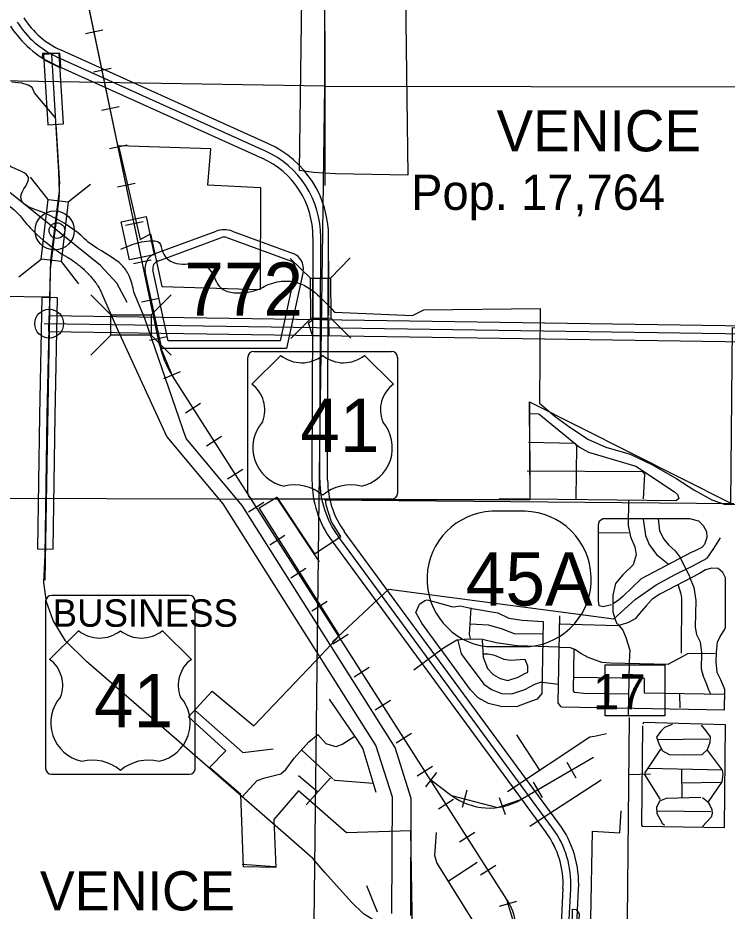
# Model space of a CAD drawing. Extents: x 408847 to 817539, y 923858 to 1151780.
# Drawn here: x 511231 to 520291, y 998249 to 1009652 of the extents above; entities that cross this region are included whole.
import ezdxf

# ---------------------------------------------------------------- set-up
doc = ezdxf.new("R2010")
doc.units = 0
for name, color, linetype in [('Airport Names', 7, 'Continuous'), ('Bridges', 7, 'Continuous'), ('Cities Incorporated Area', 7, 'Continuous'), ('Cities Incorporated Linear Boundaries', 7, 'Continuous'), ('County Route Divided Highway Outline and Fill', 7, 'Continuous'), ('Lakes and Ponds', 7, 'Continuous'), ('Level 12', 7, 'Continuous'), ('Level 23', 7, 'Continuous'), ('Level 3', 7, 'Continuous'), ('Level 39', 7, 'Continuous'), ('Level 43', 7, 'Continuous'), ('Level 6', 7, 'Continuous'), ('Local Roads Paved', 7, 'Continuous'), ('Masks for Road Features', 7, 'Continuous'), ('Narrow River Creek and Branch and Slough', 7, 'Continuous'), ('Planning Number US Highways', 7, 'Continuous'), ('Railroads', 7, 'Continuous'), ('Roadshields County Roads', 7, 'Continuous'), ('Roadshields US Highways', 7, 'Continuous'), ('Roadshields US Highways Business', 7, 'Continuous'), ('Section Lines', 7, 'Continuous'), ('Town Centers', 7, 'Continuous'), ('US Route Divided Highway Outline and Fill', 7, 'Continuous'), ('US Routes Highway Center Lines', 7, 'Continuous')]:
    doc.layers.add(name, color=color, linetype=linetype)

msp = doc.modelspace()

# ---------------------------------------------------------------- linework, layer by layer
at = {"layer": 'Bridges'}
for p, q in [((511618, 1007334), (511394, 1007618)), ((511873, 1007304), (512157, 1007528)), ((511529, 1006571), (511618, 1007334)), ((511618, 1007334), (511873, 1007304)), ((511873, 1007304), (511783, 1006541)), ((511245, 1006347), (511529, 1006571)), ((511783, 1006541), (511529, 1006571)), ((514968, 1006328), (514709, 1006582)), ((515224, 1006330), (515477, 1006588)), ((511783, 1006541), (512007, 1006257)), ((512420, 1005859), (512164, 1006115)), ((512932, 1005859), (513188, 1006115)), ((514972, 1005816), (514718, 1005558)), ((515228, 1005818), (515486, 1005564)), ((512420, 1005603), (512164, 1005347)), ((512932, 1005603), (513188, 1005347)), ((515683, 998576), (515820, 998240))]:
    msp.add_line(p, q, dxfattribs=at)
for points in [[(515224, 1006330), (515228, 1005818), (514972, 1005816), (514968, 1006328)], [(512420, 1005859), (512932, 1005859), (512932, 1005603), (512420, 1005603)]]:
    msp.add_lwpolyline(points, close=True, dxfattribs=at)
msp.add_circle((511701, 1006938), 250, dxfattribs=at)
at = {"layer": 'Cities Incorporated Area'}
for p, q in [((512516, 1008020), (512793, 1006823)), ((513696, 1007981), (512516, 1008020)), ((513659, 1007516), (513696, 1007981)), ((514336, 1007484), (513659, 1007516)), ((514332, 1006184), (514336, 1007484)), ((512793, 1006823), (512925, 1006893)), ((512925, 1006893), (513070, 1006223)), ((513070, 1006223), (514332, 1006184)), ((517768, 1004746), (517770, 1003510)), ((515085, 1002706), (514535, 1003532)), ((517770, 1003503), (515351, 1003501)), ((514096, 998850), (514513, 998820))]:
    msp.add_line(p, q, dxfattribs=at)
at = {"layer": 'Cities Incorporated Linear Boundaries'}
msp.add_line((514078, 999738), (513680, 1000083), dxfattribs=at)
for points in [[(515288, 1007663), (515007, 1007676), (514828, 1007705), (514888, 1012104), (514056, 1012044), (513225, 1011836), (513154, 1011755), (513147, 1011502), (512894, 1011153), (512686, 1010848), (512315, 1010521), (512100, 1010499), (512048, 1010573), (512078, 1010707), (512144, 1010870), (512167, 1010945), (512115, 1011041), (512048, 1011116), (511951, 1011123), (511647, 1010960), (511201, 1010811)], [(515147, 1012047), (515730, 1012047), (515730, 1010579), (516172, 1010579), (516212, 1007643), (515288, 1007663)], [(517768, 1004750), (520337, 1003455), (520360, 1005699), (523174, 1005695)], [(515344, 1003504), (517774, 1003504), (517768, 1004750)], [(514314, 1003398), (514539, 1003532), (515019, 1002811)], [(515019, 1002811), (515355, 1003031), (515237, 1003217), (515170, 1003433), (515162, 1003507), (515344, 1003504)], [(515104, 1001517), (515341, 1001768), (514314, 1003398)], [(513680, 1000083), (513886, 1000296), (513412, 1000730), (513713, 1001058), (514247, 1000615), (515104, 1001517)], [(511321, 990703), (516273, 990804), (516322, 994864), (516249, 999275), (515429, 999250), (514815, 999785), (514500, 999420), (514527, 998807), (514111, 998813), (514078, 999738)]]:
    msp.add_lwpolyline(points, dxfattribs=at)
at = {"layer": 'County Route Divided Highway Outline and Fill'}
for p, q in [((511625, 1005848), (511622, 1005648)), ((531173, 1005564), (511625, 1005848)), ((511565, 1005749), (531172, 1005464)), ((511622, 1005648), (531170, 1005364))]:
    msp.add_line(p, q, dxfattribs=at)
msp.add_lwpolyline([(518361, 998268), (518400, 998213), (518391, 998056), (518345, 998037), (518311, 998031), (518317, 998276)], close=True, dxfattribs=at)
at = {"layer": 'Lakes and Ponds'}
for points in [[(512307, 1006120), (512502, 1005674)], [(512852, 1005816), (512713, 1006150)], [(516249, 998194), (516256, 999688), (516049, 1000339), (514095, 1003427), (513379, 1004282), (512852, 1005816)], [(512502, 1005674), (513134, 1004303), (513851, 1003448), (515805, 1000360), (516012, 999709), (516005, 998219)]]:
    msp.add_lwpolyline(points, dxfattribs=at)
for points in [[(511580, 1007158), (511270, 1007376), (511365, 1007615), (511150, 1007748), (510986, 1007875), (510761, 1008043), (510597, 1008166), (510507, 1008232), (510351, 1008560), (510536, 1008801), (510589, 1008929), (510519, 1009171), (510466, 1009314), (510396, 1009548), (510478, 1009753), (510603, 1010176), (510610, 1010188)], [(510194, 1008136), (510178, 1008059), (510176, 1007945), (510170, 1007704), (510189, 1007514), (510339, 1007341), (510589, 1007316), (510837, 1007304), (511050, 1007289), (511254, 1007128), (511433, 1006925), (511793, 1006637)], [(512713, 1006150), (512657, 1006351), (512572, 1006481), (512129, 1006790), (512040, 1006872), (511580, 1007158)], [(511793, 1006637), (511834, 1006614), (511873, 1006592), (511942, 1006547), (511999, 1006504), (512047, 1006465), (512087, 1006428), (512121, 1006394), (512149, 1006364), (512196, 1006308), (512229, 1006264), (512252, 1006230), (512284, 1006177), (512307, 1006120)]]:
    msp.add_spline(points, degree=3, dxfattribs=at)
at = {"layer": 'Level 12'}
msp.add_lwpolyline([(514942, 1005759), (515006, 1005804), (515186, 1005805), (515201, 1005791), (515204, 1005606), (515185, 1005590), (515004, 1005591), (514989, 1005611)], close=True, dxfattribs=at)
msp.add_circle((511730, 1006937), 99.8, dxfattribs=at)
at = {"layer": 'Level 23'}
msp.add_lwpolyline([(512870, 1007117), (512974, 1006628), (512656, 1006561), (512552, 1007050)], close=True, dxfattribs=at)
at = {"layer": 'Level 3'}
for p, q in [((517657, 999673), (518584, 1000214)), ((516508, 999926), (516771, 999727))]:
    msp.add_line(p, q, dxfattribs=at)
msp.add_arc((517254, 1000365), 800, 232.8792, 300.2321, dxfattribs=at)
at = {"layer": 'Level 39'}
msp.add_lwpolyline([(518733, 1001394), (519496, 1001394), (519496, 1000742), (518733, 1000742)], close=True, dxfattribs=at)
at = {"layer": 'Level 6'}
for p, q in [((514434, 1008043), (511783, 1009238)), ((511701, 1009056), (514352, 1007860)), ((511714, 1008291), (511762, 1007535)), ((511758, 1007386), (511650, 1006511)), ((515000, 1006853), (514988, 1003751)), ((515188, 1003750), (515200, 1006853)), ((514997, 1006544), (514997, 1005794)), ((515197, 1006544), (515197, 1005854)), ((511644, 1006426), (511640, 1006154)), ((511640, 1006162), (511574, 1002475)), ((518143, 999367), (515401, 1003094)), ((515240, 1002975), (517981, 999248)), ((518194, 998539), (518078, 996325)), ((518278, 996315), (518394, 998529))]:
    msp.add_line(p, q, dxfattribs=at)
for centre, radius, start, end in [((512236, 1010241), 1100, 212.3802, 245.7197), ((512236, 1010241), 1300, 212.3802, 245.7197), ((513900, 1006858), 1300, 359.7797, 65.7197), ((513900, 1006858), 1100, 359.7797, 65.7197), ((510964, 1007484), 800, 352.9475, 3.6329), ((512444, 1006413), 800, 172.9475, 179.1018), ((516288, 1003746), 1300, 179.7796, 216.3338), ((516288, 1003746), 1100, 179.7796, 216.3338), ((517095, 998597), 1300, 357.0178, 36.3338), ((517095, 998597), 1100, 357.0178, 36.3338)]:
    msp.add_arc(centre, radius, start, end, dxfattribs=at)
at = {"layer": 'Local Roads Paved'}
for p, q in [((511638, 1006088), (509765, 1006105)), ((519029, 1003079), (518650, 1003072)), ((519684, 1001017), (519687, 1000844)), ((519040, 1000719), (519015, 998143)), ((517897, 1000047), (517603, 1000498)), ((519403, 1000439), (520055, 1000449)), ((514853, 1000306), (515255, 999937)), ((519241, 1000012), (519442, 1000317)), ((519275, 1000076), (520231, 1000052)), ((519707, 1000056), (519712, 999693)), ((515057, 999771), (514817, 999978)), ((514913, 999606), (515226, 999952)), ((519040, 999993), (519314, 1000003)), ((519236, 999993), (519437, 999674)), ((517770, 999335), (518682, 999924)), ((519707, 999885), (520207, 999895)), ((520084, 999517), (519403, 999527)), ((516726, 998631), (517098, 998874))]:
    msp.add_line(p, q, dxfattribs=at)
for points in [[(515139, 1019358), (515153, 1007511)], [(511712, 1008375), (511445, 1008694), (511414, 1008762), (511362, 1008792), (511282, 1008820), (511153, 1008832)], [(517764, 1004602), (517885, 1004599), (518407, 1004172), (518521, 1004109), (519125, 1003929), (519617, 1003601), (519658, 1003568), (519676, 1003517), (519639, 1003487), (517377, 1003513)], [(517753, 1004234), (518345, 1004223), (518367, 1004190), (518359, 1003506)], [(517738, 1003870), (519205, 1003863), (519224, 1003844), (519235, 1003826), (519220, 1003513)], [(519033, 1003487), (519025, 1003171), (519055, 1003027), (519110, 1002899), (519128, 1002799), (519091, 1002670), (518959, 1002542), (518867, 1002432), (518830, 1002281), (518830, 1002071), (518856, 1001983), (518882, 1001917)], [(518812, 1002159), (518760, 1002145), (518709, 1002134), (518657, 1002148), (518646, 1002211), (518646, 1003186), (518661, 1003230), (518702, 1003260), (518731, 1003260), (519812, 1003263), (519926, 1003230), (519985, 1003171), (520029, 1003094), (520033, 1003017), (520000, 1002928), (519967, 1002892), (519952, 1002881), (519882, 1002848), (519831, 1002825), (519194, 1002491), (518963, 1002270), (518900, 1002215), (518841, 1002178)], [(519220, 1003252), (519246, 1003046), (519294, 1002928), (519389, 1002800), (519536, 1002682)], [(519408, 1003256), (519426, 1003105), (519481, 1002998), (519544, 1002925), (519625, 1002848), (519691, 1002763), (519698, 1002748), (519812, 1002520)], [(518150, 1002017), (518128, 1000910), (518161, 1000862), (518179, 1000858), (520257, 1000818), (520261, 1001079), (520210, 1001201), (520165, 1001296), (520151, 1001433), (520154, 1001554), (520169, 1001683), (520202, 1001753), (520257, 1001841), (520268, 1001870), (520272, 1002503), (520235, 1002573), (520176, 1002621), (520096, 1002629), (520015, 1002606), (519937, 1002559), (519430, 1002297), (519334, 1002231), (519257, 1002146), (519172, 1002047), (519117, 1001981), (519029, 1001933), (518926, 1001900), (518889, 1001893), (518139, 1001911)], [(519812, 1002518), (519867, 1002382), (519890, 1002216), (519882, 1001874), (519901, 1001782), (519948, 1001686), (519963, 1001547), (519959, 1001341), (519985, 1001249), (520026, 1001146), (520051, 1001076), (520077, 1001024)], [(519665, 1002412), (519698, 1002298), (519709, 1002250), (519702, 1001540)], [(516643, 1001580), (516393, 1001923), (516316, 1002059), (516360, 1002166), (516430, 1002213), (516459, 1002221), (516559, 1002199), (516772, 1002136), (516801, 1002132), (516879, 1002147), (517033, 1002114), (517364, 1002055), (517504, 1001989), (517673, 1001963), (517942, 1001948), (517923, 1001025), (517864, 1000955), (517743, 1000914), (517600, 1000855), (517401, 1000863), (517243, 1000900), (517110, 1000973), (517011, 1001076), (516636, 1001588)], [(517018, 1002121), (516996, 1001779), (517007, 1001731)], [(517011, 1001915), (517239, 1001904), (517405, 1001856), (517570, 1001794), (517931, 1001787)], [(518889, 1001915), (518959, 1001834), (518999, 1001742), (519047, 1001580), (519040, 1001425), (519025, 1000755)], [(518144, 1001617), (517603, 1001636), (517342, 1001676), (517166, 1001717), (516978, 1001720), (516838, 1001706), (516669, 1001606), (516290, 1001327)], [(516849, 1001702), (516893, 1001533), (517184, 1001146), (517280, 1001080), (517408, 1001025), (517541, 1001021), (517706, 1001080), (517835, 1001146), (517905, 1001172), (517931, 1001172), (518137, 1001146)], [(517162, 1001706), (517173, 1001492), (517232, 1001345), (517302, 1001271), (517390, 1001220), (517489, 1001194), (517622, 1001235), (517699, 1001279), (517743, 1001301), (517743, 1001378), (517710, 1001459), (517522, 1001448), (517441, 1001463), (517324, 1001511), (517239, 1001529), (517166, 1001529)], [(518150, 1001617), (518286, 1001613), (518352, 1001587), (518426, 1001539), (518510, 1001491), (518573, 1001469), (518687, 1001429), (518805, 1001418), (519536, 1001403), (519720, 1001499), (519790, 1001536), (519996, 1001543), (520140, 1001539)], [(518334, 1001591), (518326, 1001061), (518337, 1001046), (518382, 1001039), (518455, 1001031), (519029, 1001024)], [(520254, 1001013), (519235, 1001031), (519235, 1001219), (518341, 1001230)], [(515207, 1000956), (515568, 1000426), (515638, 1000320), (515803, 999768)], [(513493, 1000813), (514104, 1000272), (514494, 1000320)], [(519211, 1000616), (519197, 999345), (519207, 999335), (520256, 999316), (520271, 1000626), (519221, 1000655), (519216, 1000635)], [(519589, 1000631), (519491, 1000591), (519442, 1000547), (519388, 1000469), (519422, 1000375), (519466, 1000297), (519550, 1000248), (519741, 1000243), (519972, 1000248), (520040, 1000312), (520075, 1000405), (520079, 1000474), (520021, 1000552), (519962, 1000621)], [(517485, 999777), (518535, 1000474), (518598, 1000483), (518750, 1000518)], [(514098, 999706), (514288, 999915), (514387, 999952), (514589, 1000003), (514652, 1000055), (514759, 1000202), (514946, 1000408), (515061, 1000505)], [(515534, 1000477), (515384, 1000382), (515292, 1000346), (515171, 1000386), (515061, 1000505)], [(520035, 1000302), (520227, 1000047), (520236, 999998), (520222, 999899), (520050, 999644)], [(515262, 999930), (515281, 999919), (515768, 999884)], [(519957, 999698), (519511, 999688), (519427, 999654), (519388, 999571), (519393, 999497), (519437, 999419), (519462, 999370), (519491, 999345)], [(519976, 999698), (520040, 999649), (520070, 999600), (520094, 999546), (520099, 999492), (520089, 999448), (520026, 999384), (519976, 999330)], [(518549, 998146), (518569, 999271), (518922, 999247), (518937, 999531)], [(516573, 999252), (516553, 998958), (516583, 998860), (517068, 998084), (517103, 998030)]]:
    msp.add_lwpolyline(points, dxfattribs=at)
at = {"layer": 'Masks for Road Features'}
msp.add_lwpolyline([(511542, 1009150), (511582, 1009108), (511758, 1009024), (511780, 1009030), (511766, 1009202), (511546, 1009196)], close=True, dxfattribs=at)
at = {"layer": 'Narrow River Creek and Branch and Slough'}
for p, q in [((515275, 1005895), (516270, 1005852)), ((516270, 1005852), (516417, 1005926)), ((516417, 1005926), (517902, 1005940)), ((517902, 1005940), (517895, 1004734)), ((517895, 1004734), (518094, 1004565)), ((518094, 1004565), (518282, 1004426)), ((518282, 1004426), (518522, 1004269)), ((518522, 1004269), (518742, 1004172)), ((518742, 1004172), (519053, 1004082)), ((519053, 1004082), (519331, 1003952)), ((519331, 1003952), (519650, 1003768)), ((519650, 1003768), (519867, 1003629)), ((519867, 1003629), (520097, 1003500)), ((520097, 1003500), (520266, 1003441)), ((520266, 1003441), (520433, 1003445)), ((520119, 1002877), (520207, 1003016)), ((520035, 1002753), (520119, 1002877)), ((519853, 1002657), (520035, 1002753)), ((519626, 1002548), (519853, 1002657)), ((519383, 1002416), (519626, 1002548)), ((515251, 1001688), (515970, 1002360)), ((515970, 1002360), (518844, 1001981)), ((519116, 1002225), (519383, 1002416)), ((518844, 1001981), (519116, 1002225))]:
    msp.add_line(p, q, dxfattribs=at)
msp.add_lwpolyline([(512628, 1006019), (512494, 1006267), (512288, 1006490), (510641, 1007809)], dxfattribs=at)
msp.add_spline([(512547, 1006701), (512660, 1006746), (512913, 1006806), (513037, 1006784), (513081, 1006660), (513335, 1006507), (513577, 1006511), (513720, 1006382), (513753, 1006311), (513819, 1006210), (513972, 1006146), (514149, 1006148), (514308, 1006188), (514402, 1006234), (514517, 1006275), (514739, 1006286), (515275, 1005895)], degree=3, dxfattribs=at)
at = {"layer": 'Planning Number US Highways'}
for p, q in [((517709, 1003354), (517285, 1003354)), ((517217, 1001626), (517770, 1001626))]:
    msp.add_line(p, q, dxfattribs=at)
for centre, radius, start, end in [((517324, 1002487), 867, 92.5588, 262.9755), ((517689, 1002488), 866, 275.316, 88.7032)]:
    msp.add_arc(centre, radius, start, end, dxfattribs=at)
at = {"layer": 'Railroads'}
for p, q in [((513042, 1005482), (511050, 1014994)), ((512093, 1009452), (512318, 1009499)), ((512196, 1008963), (512421, 1009010)), ((512298, 1008474), (512523, 1008521)), ((512401, 1007984), (512626, 1008031)), ((512503, 1007495), (512728, 1007542)), ((512606, 1007005), (512831, 1007053)), ((512708, 1006516), (512933, 1006563)), ((512811, 1006027), (513036, 1006074)), ((512913, 1005537), (513138, 1005584)), ((513094, 1005050), (513307, 1005137)), ((517478, 998398), (513206, 1005081)), ((513371, 1004609), (513565, 1004733)), ((513640, 1004188), (513834, 1004312)), ((513910, 1003767), (514103, 1003891)), ((514179, 1003346), (514373, 1003469)), ((514448, 1002924), (514642, 1003048)), ((514718, 1002503), (514911, 1002627)), ((514987, 1002082), (515181, 1002206)), ((515256, 1001660), (515450, 1001784)), ((515525, 1001239), (515719, 1001363)), ((515795, 1000818), (515989, 1000942)), ((516064, 1000397), (516258, 1000520)), ((516333, 999975), (516527, 1000099)), ((518244, 1000149), (518360, 999950)), ((516577, 1000018), (516438, 999834)), ((517812, 999897), (517928, 999698)), ((516965, 999795), (516906, 999572)), ((516603, 999554), (516796, 999678)), ((517380, 999700), (517455, 999483)), ((516872, 999133), (517066, 999257)), ((517141, 998711), (517335, 998835)), ((517383, 998313), (517604, 998378))]:
    msp.add_line(p, q, dxfattribs=at)
for points in [[(517607, 997362), (517604, 997971), (517604, 997971), (517478, 998398), (517478, 998398), (513206, 1005081), (513206, 1005081), (513042, 1005482), (513042, 1005482), (511050, 1014994), (510079, 1019797), (501500, 1060485)], [(516508, 999926), (516771, 999727), (516771, 999727), (517359, 999571), (517657, 999673), (517657, 999673), (518584, 1000214)]]:
    msp.add_lwpolyline(points, dxfattribs=at)
for centre, radius, start, end in [((514217, 1005728), 1200, 191.8291, 212.5882), ((516804, 997967), 800, 0.3104, 32.5882)]:
    msp.add_arc(centre, radius, start, end, dxfattribs=at)
at = {"layer": 'Roadshields County Roads'}
for p, q in [((512984, 1006642), (513763, 1006929)), ((513970, 1006929), (514748, 1006643)), ((513018, 1006548), (513832, 1006847)), ((513901, 1006847), (514714, 1006549)), ((513068, 1005430), (512857, 1006413)), ((513149, 1005530), (512955, 1006434)), ((514777, 1006434), (514583, 1005530)), ((514875, 1006413), (514664, 1005430)), ((514583, 1005530), (513149, 1005530)), ((514664, 1005430), (513068, 1005430))]:
    msp.add_line(p, q, dxfattribs=at)
for centre, radius, start, end in [((513867, 1006647), 300, 69.827, 110.173), ((513867, 1006754), 100, 69.827, 110.173), ((513053, 1006455), 200, 110.173, 192.0999), ((514679, 1006455), 200, 347.9001, 69.827), ((513053, 1006455), 100, 110.173, 192.0999), ((514679, 1006455), 100, 347.9001, 69.827)]:
    msp.add_arc(centre, radius, start, end, dxfattribs=at)
at = {"layer": 'Roadshields US Highways'}
for p, q in [((514168, 1003584), (514168, 1005318)), ((514588, 1005343), (514218, 1004977)), ((514243, 1005393), (516005, 1005393)), ((514588, 1005343), (514588, 1005343)), ((515124, 1005341), (515124, 1005341)), ((516030, 1004977), (515660, 1005343)), ((516080, 1005318), (516080, 1003584)), ((516005, 1003509), (514243, 1003509))]:
    msp.add_line(p, q, dxfattribs=at)
for centre, radius, start, end in [((514243, 1005318), 75, 90, 180), ((514857, 1005679), 430, 231.2915, 308.3626), ((515391, 1005679), 430, 231.6374, 308.7085), ((516005, 1005318), 75, 0, 90), ((513977, 1004647), 409, 338.3056, 53.8199), ((516271, 1004647), 409, 126.1801, 201.6944), ((514734, 1004165), 501, 138.7831, 258.2378), ((515514, 1004165), 501, 281.7622, 41.2169), ((514765, 1003132), 558, 49.9101, 103.7765), ((515484, 1003132), 558, 76.2235, 130.0899), ((514243, 1003584), 75, 180, 270), ((516005, 1003584), 75, 270, 0)]:
    msp.add_arc(centre, radius, start, end, dxfattribs=at)
at = {"layer": 'Roadshields US Highways Business'}
for p, q in [((513422, 1002279), (511661, 1002279)), ((511586, 1002204), (511586, 1000071)), ((513497, 1000071), (513497, 1002204)), ((511636, 1001463), (512006, 1001829)), ((512006, 1001829), (512006, 1001829)), ((512542, 1001827), (512542, 1001827)), ((513078, 1001829), (513447, 1001463)), ((511636, 1001463), (511636, 1001463)), ((511661, 999996), (513422, 999996))]:
    msp.add_line(p, q, dxfattribs=at)
for centre, radius, start, end in [((511661, 1002204), 75, 90, 180), ((513422, 1002204), 75, 0, 90), ((512275, 1002165), 430, 231.2915, 308.3626), ((512809, 1002165), 430, 231.6374, 308.7085), ((511395, 1001133), 409, 338.3056, 53.8199), ((513689, 1001133), 409, 126.1801, 201.6944), ((512152, 1000652), 501, 138.7831, 258.2378), ((512932, 1000652), 501, 281.7622, 41.2169), ((512182, 999619), 558, 49.9101, 103.7765), ((512901, 999619), 558, 76.2235, 130.0899), ((511661, 1000071), 75, 180, 270), ((513422, 1000071), 75, 270, 0)]:
    msp.add_arc(centre, radius, start, end, dxfattribs=at)
at = {"layer": 'Section Lines'}
for p, q in [((515147, 1008779), (509825, 1008867)), ((515147, 1008779), (520428, 1008770)), ((515146, 1003502), (509727, 1003518)), ((515074, 1003514), (515011, 998103)), ((515146, 1003501), (520375, 1003453))]:
    msp.add_line(p, q, dxfattribs=at)
for points in [[(515149, 1014053), (515147, 1008779)], [(515147, 1008779), (515074, 1003514)]]:
    msp.add_lwpolyline(points, dxfattribs=at)
at = {"layer": 'Town Centers'}
msp.add_circle((511631, 1005748), 184, dxfattribs=at)
at = {"layer": 'US Route Divided Highway Outline and Fill'}
for p, q in [((511757, 1009196), (511558, 1009183)), ((511558, 1009183), (511615, 1008285)), ((511814, 1008298), (511757, 1009196)), ((511615, 1008285), (511814, 1008298)), ((511739, 1006080), (511539, 1006083)), ((511480, 1002873), (511680, 1002871))]:
    msp.add_line(p, q, dxfattribs=at)
for points in [[(511539, 1006083), (511507, 1004577), (511480, 1002873)], [(511680, 1002871), (511707, 1004573), (511739, 1006080)]]:
    msp.add_lwpolyline(points, dxfattribs=at)
at = {"layer": 'US Routes Highway Center Lines'}
for p, q in [((514393, 1007951), (511742, 1009147)), ((515088, 1003750), (515100, 1006853)), ((518062, 999308), (515321, 1003035)), ((518178, 996320), (518294, 998534))]:
    msp.add_line(p, q, dxfattribs=at)
msp.add_lwpolyline([(518258, 995824), (516782, 997628), (516628, 997761), (516363, 997883), (515757, 998147), (515645, 998213), (515494, 998364), (515152, 998742), (514998, 998920), (514683, 999196), (513160, 1000523), (512107, 1001436), (511841, 1001699), (511681, 1001961), (511597, 1002199), (511562, 1002444), (511579, 1002794), (511607, 1004575), (511642, 1006251), (511653, 1006555), (511750, 1007346), (511764, 1007437), (511754, 1007686), (511664, 1009186)], dxfattribs=at)
for centre, start, end in [((512236, 1010241), 212.3802, 245.7197), ((513900, 1006858), 359.7797, 65.7197), ((516288, 1003746), 179.7796, 216.3338), ((517095, 998597), 357.0178, 36.3338)]:
    msp.add_arc(centre, 1200, start, end, dxfattribs=at)

# ---------------------------------------------------------------- texts
at = {"layer": 'Airport Names'}
msp.add_text('VENICE', height=500, rotation=0, dxfattribs=at).set_placement((511512, 998258))
at = {"layer": 'Level 39'}
for s, height, p in [('VENICE', 525, (517345, 1007948)), ('Pop. 17,764', 450, (516253, 1007201))]:
    msp.add_text(s, height=height, rotation=360, dxfattribs=at).set_placement(p)
at = {"layer": 'Level 43'}
msp.add_text('17', height=450, rotation=359.6504, dxfattribs=at).set_placement((518579, 1000827))
at = {"layer": 'Planning Number US Highways'}
msp.add_text('45A', height=680, dxfattribs=at).set_placement((516953, 1002150))
at = {"layer": 'Roadshields County Roads'}
msp.add_text('772', height=680, dxfattribs=at).set_placement((513357, 1005849))
at = {"layer": 'Roadshields US Highways'}
msp.add_text('41', height=680, dxfattribs=at).set_placement((514839, 1004110))
at = {"layer": 'Roadshields US Highways Business'}
for s, height, p in [('BUSINESS', 350, (511675, 1001879)), ('41', 680, (512202, 1000597))]:
    msp.add_text(s, height=height, dxfattribs=at).set_placement(p)

doc.saveas('drawing.dxf')
